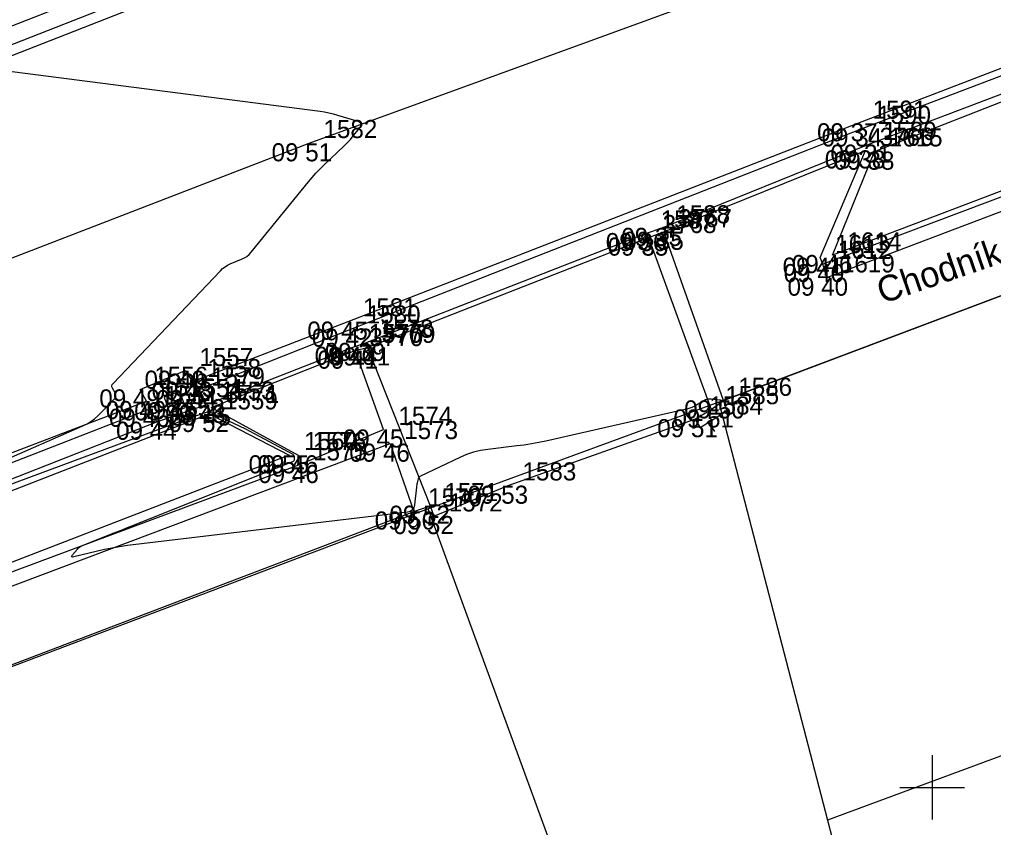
# Model space of a CAD drawing. Extents: x -703403 to -701924, y -1022520 to -1021856.
# Drawn here: x -702964.13 to -702949.05, y -1022000.62 to -1021988.11 of the extents above; entities that cross this region are included whole.
import ezdxf

# ---------------------------------------------------------------- set-up
doc = ezdxf.new("R2010")
doc.units = 0
for name, color, linetype in [('Ex_Minor Contours', 7, 'Continuous'), ('Z_body', 7, 'Continuous'), ('Z_body_cisla', 7, 'Continuous'), ('Z_body_vysky_redukovane', 7, 'Continuous'), ('Z_budova', 7, 'Continuous'), ('Z_chodnik', 7, 'Continuous'), ('Z_hektometricka_sit', 7, 'Continuous'), ('Z_katastr_hranice', 7, 'Continuous'), ('Z_katastr_vnitrni_kresba', 7, 'Continuous'), ('Z_komunikace', 7, 'Continuous'), ('Z_komunikace_osa', 7, 'Continuous'), ('Z_obruba', 7, 'Continuous'), ('Z_ploty', 7, 'Continuous'), ('Z_ploty_znacky', 7, 'Continuous'), ('Z_popisy', 7, 'Continuous'), ('Z_rozhranni', 7, 'Continuous'), ('Z_site_kanalizace_znaky', 7, 'Continuous'), ('Z_vstupy', 7, 'Continuous'), ('Z_zlabek', 7, 'Continuous')]:
    doc.layers.add(name, color=color, linetype=linetype)

# ---------------------------------------------------------------- blocks, each defined once
blk = doc.blocks.new('POINT_DISPLAY')
blk.add_line((0, 0), (0, 0))
blk = doc.blocks.new('Z46260')
for p, q in [((0.13, 0.13), (-0.13, 0.13)), ((-0.13, 0.13), (-0.13, -0.13)), ((0.13, 0), (-0.13, 0)), ((0.13, -0.13), (0.13, 0.13)), ((-0.13, -0.13), (0.13, -0.13))]:
    blk.add_line(p, q)
blk = doc.blocks.new('Z210')
blk.add_line((0, 0), (0, 0.17))

msp = doc.modelspace()

# ---------------------------------------------------------------- linework, layer by layer
at = {"layer": 'Ex_Minor Contours'}
for points in [[(-702964.465, -1021994.983), (-702963.143, -1021994.403), (-702963.08, -1021994.373), (-702963.022, -1021994.336), (-702962.967, -1021994.294), (-702962.915, -1021994.247), (-702962.652, -1021993.979), (-702962.639, -1021993.962), (-702962.633, -1021993.944), (-702962.634, -1021993.925), (-702962.642, -1021993.905), (-702962.688, -1021993.822), (-702962.696, -1021993.802), (-702962.697, -1021993.783), (-702962.691, -1021993.764), (-702962.678, -1021993.747), (-702961.015, -1021992.004), (-702960.981, -1021991.971), (-702960.944, -1021991.943), (-702960.905, -1021991.919), (-702960.863, -1021991.899), (-702960.688, -1021991.826), (-702960.645, -1021991.806), (-702960.607, -1021991.781), (-702960.572, -1021991.751), (-702960.54, -1021991.717), (-702959.65, -1021990.625), (-702959.594, -1021990.559), (-702959.536, -1021990.494), (-702959.476, -1021990.431), (-702959.413, -1021990.369), (-702959.101, -1021990.072), (-702959.068, -1021990.039), (-702959.036, -1021990.006), (-702959.004, -1021989.972), (-702958.974, -1021989.936), (-702958.856, -1021989.794), (-702958.836, -1021989.761), (-702958.834, -1021989.733), (-702958.85, -1021989.711), (-702958.885, -1021989.695), (-702959.199, -1021989.6), (-702959.267, -1021989.581), (-702959.335, -1021989.565), (-702959.403, -1021989.551), (-702959.472, -1021989.541), (-702964.562, -1021988.884)], [(-702953.23, -1021994.01), (-702953.418, -1021993.99), (-702953.449, -1021993.989), (-702953.478, -1021993.993), (-702953.507, -1021994.002), (-702953.535, -1021994.016), (-702953.656, -1021994.089), (-702953.686, -1021994.106), (-702953.717, -1021994.119), (-702953.749, -1021994.131), (-702953.782, -1021994.14), (-702955.976, -1021994.639), (-702956.087, -1021994.663), (-702956.199, -1021994.684), (-702956.312, -1021994.702), (-702956.425, -1021994.716), (-702956.878, -1021994.769), (-702956.99, -1021994.786), (-702957.1, -1021994.813), (-702957.207, -1021994.848), (-702957.311, -1021994.893), (-702957.917, -1021995.181), (-702957.93, -1021995.189), (-702957.941, -1021995.199), (-702957.949, -1021995.211), (-702957.954, -1021995.226), (-702957.969, -1021995.289), (-702957.973, -1021995.304), (-702957.976, -1021995.32), (-702957.978, -1021995.336), (-702957.98, -1021995.352), (-702958.009, -1021995.628), (-702958.02, -1021995.673), (-702958.043, -1021995.707), (-702958.077, -1021995.73), (-702958.122, -1021995.742), (-702962.455, -1021996.259), (-702962.545, -1021996.271), (-702962.634, -1021996.285), (-702962.723, -1021996.302), (-702962.811, -1021996.321), (-702963.285, -1021996.432), (-702963.307, -1021996.435), (-702963.317, -1021996.431), (-702963.316, -1021996.42), (-702963.303, -1021996.402), (-702963.23, -1021996.315), (-702963.211, -1021996.295), (-702963.19, -1021996.277), (-702963.166, -1021996.263), (-702963.141, -1021996.251), (-702962.7, -1021996.077), (-702962.617, -1021996.045), (-702962.535, -1021996.012), (-702962.453, -1021995.98), (-702962.371, -1021995.947), (-702959.886, -1021994.951), (-702959.878, -1021994.946), (-702959.872, -1021994.94), (-702959.869, -1021994.932), (-702959.868, -1021994.923), (-702959.871, -1021994.881), (-702959.873, -1021994.871), (-702959.876, -1021994.863), (-702959.882, -1021994.856), (-702959.891, -1021994.85), (-702960.402, -1021994.573), (-702960.479, -1021994.532), (-702960.556, -1021994.492), (-702960.634, -1021994.453), (-702960.712, -1021994.415), (-702961.177, -1021994.194), (-702961.182, -1021994.192), (-702961.186, -1021994.191), (-702961.196, -1021994.19), (-702961.201, -1021994.189), (-702961.206, -1021994.19), (-702961.345, -1021994.235), (-702961.369, -1021994.242), (-702961.392, -1021994.251), (-702961.416, -1021994.259), (-702961.44, -1021994.267), (-702964.673, -1021995.46)]]:
    msp.add_lwpolyline(points, dxfattribs=at)
at = {"layer": 'Z_budova'}
for p, q in [((-702953.23, -1021994.01), (-702941.96, -1021989.76)), ((-702953.23, -1021994.01), (-702953.18, -1021994.16)), ((-702966.5, -1021998.96), (-702958.02, -1021995.73)), ((-702958.02, -1021995.73), (-702957.77, -1021995.64)), ((-702957.77, -1021995.64), (-702957.71, -1021995.8))]:
    msp.add_line(p, q, dxfattribs=at)
at = {"layer": 'Z_chodnik'}
for p, q in [((-702942.41, -1021988.4), (-702951.69, -1021991.9)), ((-702951.73, -1021991.8), (-702951.03, -1021990.14)), ((-702951.69, -1021991.9), (-702951.73, -1021991.8)), ((-702961.16, -1021994.12), (-702959.81, -1021994.86)), ((-702959.8, -1021995.01), (-702959.81, -1021994.86)), ((-702970.83, -1021999.11), (-702959.8, -1021995.01))]:
    msp.add_line(p, q, dxfattribs=at)
at = {"layer": 'Z_hektometricka_sit'}
for p, q in [((-702950, -1021999.5), (-702950, -1022000.5)), ((-702950.5, -1022000), (-702949.5, -1022000))]:
    msp.add_line(p, q, dxfattribs=at)
at = {"layer": 'Z_katastr_hranice'}
for p, q in [((-702941.75, -1021989.68), (-702953.3, -1021994.04)), ((-702953.3, -1021994.04), (-702957.8, -1021995.69)), ((-702953.3, -1021994.04), (-702951.62, -1022000.51)), ((-702957.8, -1021995.69), (-702966.8, -1021999.1)), ((-702951.62, -1022000.51), (-702949.18, -1022009.85))]:
    msp.add_line(p, q, dxfattribs=at)
at = {"layer": 'Z_katastr_vnitrni_kresba'}
for p, q in [((-702951.85, -1022011.94), (-702957.8, -1021995.69)), ((-702947.17, -1021998.86), (-702951.62, -1022000.51))]:
    msp.add_line(p, q, dxfattribs=at)
at = {"layer": 'Z_komunikace'}
for p, q in [((-702966.7, -1021989.63), (-702956.88, -1021985.79)), ((-702951.15, -1021989.72), (-702943.58, -1021986.81)), ((-702959.04, -1021992.79), (-702951.15, -1021989.72)), ((-702961.45, -1021993.72), (-702959.04, -1021992.79)), ((-702962.26, -1021993.84), (-702961.56, -1021993.55)), ((-702961.56, -1021993.55), (-702961.45, -1021993.72)), ((-702962.16, -1021994.02), (-702962.26, -1021993.84)), ((-702970.7, -1021997.29), (-702962.16, -1021994.02))]:
    msp.add_line(p, q, dxfattribs=at)
at = {"layer": 'Z_komunikace_osa'}
for p, q in [((-702959.64, -1021990.03), (-702952.05, -1021987.26)), ((-702967.67, -1021993.13), (-702959.64, -1021990.03))]:
    msp.add_line(p, q, dxfattribs=at)
at = {"layer": 'Z_obruba'}
for p, q in [((-702966.79, -1021989.5), (-702956.93, -1021985.63)), ((-702951.08, -1021989.8), (-702943.59, -1021986.95)), ((-702950.89, -1021990.16), (-702943.42, -1021987.22)), ((-702942.49, -1021988.32), (-702951.54, -1021991.76)), ((-702958.97, -1021992.9), (-702951.08, -1021989.8)), ((-702954.15, -1021991.4), (-702951.03, -1021990.14)), ((-702951.54, -1021991.76), (-702950.89, -1021990.16)), ((-702958.74, -1021993.19), (-702954.39, -1021991.49)), ((-702954.39, -1021991.49), (-702954.15, -1021991.4)), ((-702961.38, -1021993.85), (-702958.97, -1021992.9)), ((-702961.16, -1021994.12), (-702958.93, -1021993.24)), ((-702958.93, -1021993.24), (-702958.74, -1021993.19)), ((-702970.64, -1021997.47), (-702962.11, -1021994.14)), ((-702970.44, -1021997.81), (-702961.19, -1021994.22)), ((-702961.19, -1021994.22), (-702959.95, -1021994.86)), ((-702959.95, -1021994.86), (-702970.74, -1021999.02))]:
    msp.add_line(p, q, dxfattribs=at)
at = {"layer": 'Z_ploty'}
for p, q in [((-702953.42, -1021994.15), (-702953.23, -1021994.01)), ((-702953.67, -1021994.3), (-702953.42, -1021994.15)), ((-702953.33, -1021994.27), (-702953.18, -1021994.16)), ((-702953.67, -1021994.3), (-702953.59, -1021994.43)), ((-702953.59, -1021994.43), (-702953.33, -1021994.27))]:
    msp.add_line(p, q, dxfattribs=at)
at = {"layer": 'Z_rozhranni'}
for p, q in [((-702961.38, -1021993.85), (-702961.45, -1021993.72)), ((-702961.24, -1021994.08), (-702961.38, -1021993.85)), ((-702962.16, -1021994.02), (-702962.11, -1021994.14)), ((-702962.11, -1021994.14), (-702962, -1021994.34))]:
    msp.add_line(p, q, dxfattribs=at)
at = {"layer": 'Z_vstupy'}
for p, q in [((-702956.56, -1021995.33), (-702953.67, -1021994.3)), ((-702957.71, -1021995.8), (-702956.56, -1021995.33))]:
    msp.add_line(p, q, dxfattribs=at)
at = {"layer": 'Z_zlabek'}
for p, q in [((-702950.99, -1021990.05), (-702943.42, -1021987.18)), ((-702966.87, -1021989.24), (-702962.53, -1021987.54)), ((-702951.63, -1021992.11), (-702942.39, -1021988.6)), ((-702954.18, -1021991.34), (-702950.99, -1021990.05)), ((-702954.42, -1021991.42), (-702954.18, -1021991.34)), ((-702958.77, -1021993.12), (-702954.42, -1021991.42)), ((-702954.39, -1021991.49), (-702953.42, -1021994.15)), ((-702953.23, -1021994.01), (-702954.15, -1021991.4)), ((-702951.63, -1021992.11), (-702951.69, -1021991.9)), ((-702961.24, -1021994.08), (-702958.95, -1021993.18)), ((-702958.95, -1021993.18), (-702958.77, -1021993.12)), ((-702958.49, -1021994.46), (-702958.93, -1021993.24)), ((-702958.74, -1021993.19), (-702957.77, -1021995.64)), ((-702962, -1021994.34), (-702961.24, -1021994.08)), ((-702970.56, -1021997.71), (-702962, -1021994.34)), ((-702959.8, -1021995.01), (-702958.49, -1021994.46)), ((-702966.88, -1021997.88), (-702958.39, -1021994.68)), ((-702958.39, -1021994.68), (-702958.02, -1021995.73))]:
    msp.add_line(p, q, dxfattribs=at)

# ---------------------------------------------------------------- block references
at = {"layer": 'Z_body'}
for p in [(-702951.15, -1021989.72), (-702951.08, -1021989.8), (-702959.64, -1021990.03), (-702951.03, -1021990.14), (-702950.99, -1021990.05), (-702950.89, -1021990.16), (-702954.18, -1021991.34), (-702954.42, -1021991.42), (-702954.39, -1021991.49), (-702954.15, -1021991.4), (-702951.73, -1021991.8), (-702951.54, -1021991.76), (-702951.69, -1021991.9), (-702951.63, -1021992.11), (-702959.04, -1021992.79), (-702958.97, -1021992.9), (-702958.95, -1021993.18), (-702958.77, -1021993.12), (-702958.93, -1021993.24), (-702958.74, -1021993.19), (-702961.56, -1021993.55), (-702961.45, -1021993.72), (-702962.26, -1021993.84), (-702961.38, -1021993.85), (-702962.16, -1021994.02), (-702961.72, -1021994.04), (-702961.24, -1021994.08), (-702953.23, -1021994.01), (-702962.11, -1021994.14), (-702961.19, -1021994.22), (-702961.16, -1021994.12), (-702953.42, -1021994.15), (-702962, -1021994.34), (-702953.67, -1021994.3), (-702958.49, -1021994.46), (-702958.39, -1021994.68), (-702959.95, -1021994.86), (-702959.81, -1021994.86), (-702959.8, -1021995.01), (-702956.56, -1021995.33), (-702958.02, -1021995.73), (-702957.77, -1021995.64), (-702957.71, -1021995.8)]:
    msp.add_blockref('POINT_DISPLAY', p, dxfattribs=at)
at = {"layer": 'Z_ploty_znacky', "rotation": -148}
msp.add_blockref('Z210', (-702953.46, -1021994.35), dxfattribs=at)
at = {"layer": 'Z_site_kanalizace_znaky', "rotation": 19.8}
msp.add_blockref('Z46260', (-702961.72, -1021994.04), dxfattribs=at)

# ---------------------------------------------------------------- texts
at = {"layer": 'Z_body_cisla'}
for s, p in [('1591', (-702950.92, -1021989.65)), ('1590', (-702950.85, -1021989.73)), ('1582', (-702959.42, -1021989.95)), ('1589', (-702950.76, -1021989.98)), ('3766', (-702950.81, -1021990.07)), ('1615', (-702950.67, -1021990.08)), ('1587', (-702954.2, -1021991.35)), ('1588', (-702953.96, -1021991.27)), ('3767', (-702953.93, -1021991.33)), ('3768', (-702954.17, -1021991.42)), ('1613', (-702951.5, -1021991.73)), ('1614', (-702951.31, -1021991.69)), ('1612', (-702951.46, -1021991.82)), ('1619', (-702951.41, -1021992.03)), ('1581', (-702958.81, -1021992.71)), ('1580', (-702958.75, -1021992.82)), ('1577', (-702958.72, -1021993.11)), ('1578', (-702958.55, -1021993.04)), ('3769', (-702958.52, -1021993.12)), ('3770', (-702958.71, -1021993.17)), ('1557', (-702961.34, -1021993.48)), ('1558', (-702961.22, -1021993.65)), ('1556', (-702962.04, -1021993.77)), ('1579', (-702961.16, -1021993.78)), ('1555', (-702961.93, -1021993.95)), ('1554', (-702961.5, -1021993.96)), ('1553', (-702961.01, -1021994)), ('3771', (-702960.94, -1021994.05)), ('1586', (-702953, -1021993.94)), ('1551', (-702961.88, -1021994.07)), ('1559', (-702960.96, -1021994.15)), ('1585', (-702953.2, -1021994.07)), ('1552', (-702961.78, -1021994.27)), ('1584', (-702953.45, -1021994.23)), ('1574', (-702958.26, -1021994.39)), ('1573', (-702958.17, -1021994.61)), ('1560', (-702959.72, -1021994.78)), ('1576', (-702959.59, -1021994.78)), ('1575', (-702959.58, -1021994.94)), ('1583', (-702956.34, -1021995.25)), ('1571', (-702957.55, -1021995.57)), ('1570', (-702957.8, -1021995.65)), ('1572', (-702957.48, -1021995.73))]:
    msp.add_text(s, height=0.28, dxfattribs=at).set_placement(p)
at = {"layer": 'Z_body_vysky_redukovane'}
for s, p in [('09 37', (-702951.78, -1021990)), ('09 34', (-702951.71, -1021990.08)), ('09 51', (-702960.223, -1021990.31)), ('09 38', (-702951.66, -1021990.42)), ('09 31', (-702951.573, -1021990.33)), ('09 38', (-702951.52, -1021990.44)), ('09 35', (-702954.81, -1021991.62)), ('09 36', (-702955.05, -1021991.7)), ('09 35', (-702955.02, -1021991.77)), ('09 35', (-702954.78, -1021991.68)), ('09 41', (-702952.313, -1021992.08)), ('09 46', (-702952.17, -1021992.04)), ('09 40', (-702952.297, -1021992.18)), ('09 40', (-702952.237, -1021992.39)), ('09 45', (-702959.67, -1021993.07)), ('09 42', (-702959.6, -1021993.18)), ('09 40', (-702959.557, -1021993.46)), ('09 39', (-702959.4, -1021993.4)), ('09 41', (-702959.513, -1021993.52)), ('09 41', (-702959.323, -1021993.47)), ('09 49', (-702962.19, -1021993.83)), ('09 48', (-702962.08, -1021994)), ('09 49', (-702962.89, -1021994.12)), ('09 44', (-702962.01, -1021994.13)), ('09 49', (-702962.79, -1021994.3)), ('09 43', (-702962.35, -1021994.32)), ('09 43', (-702961.87, -1021994.36)), ('09 50', (-702953.837, -1021994.29)), ('09 46', (-702962.74, -1021994.42)), ('09 52', (-702961.82, -1021994.5)), ('09 45', (-702961.79, -1021994.4)), ('09 51', (-702954.003, -1021994.43)), ('09 44', (-702962.63, -1021994.62)), ('09 51', (-702954.253, -1021994.58)), ('09 45', (-702959.12, -1021994.74)), ('09 46', (-702959.02, -1021994.96)), ('09 55', (-702960.58, -1021995.14)), ('09 46', (-702960.44, -1021995.14)), ('09 46', (-702960.43, -1021995.29)), ('09 53', (-702957.19, -1021995.61)), ('09 50', (-702958.627, -1021996.01)), ('09 52', (-702958.4, -1021995.92)), ('09 52', (-702958.34, -1021996.08))]:
    msp.add_text(s, height=0.28, dxfattribs=at).set_placement(p)
at = {"layer": 'Z_popisy'}
msp.add_text('Chodník - zámk. dlažba', height=0.4, rotation=18.9, dxfattribs=at).set_placement((-702950.77, -1021992.52))

doc.saveas('drawing.dxf')
